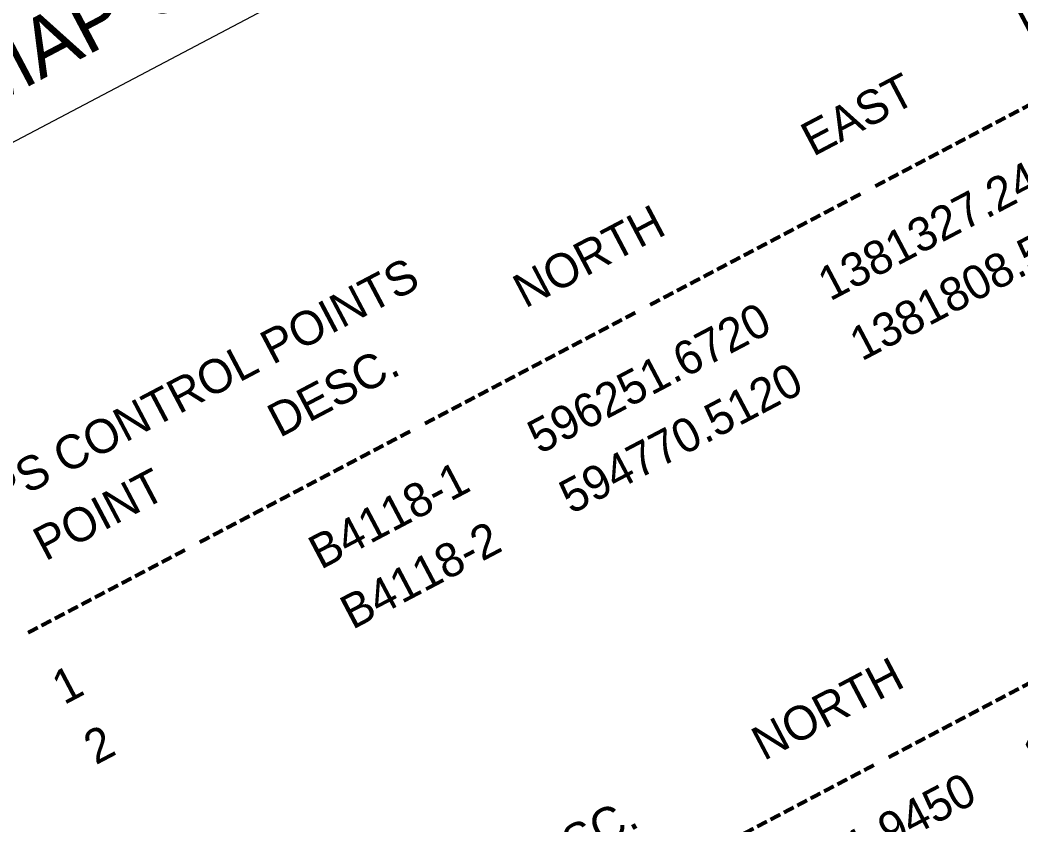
# Model space of a CAD drawing. Extents: x 1379448 to 1382868, y 593769 to 596827.
# Drawn here: x 1379935.9 to 1380243, y 594832.7 to 595079.7 of the extents above; entities that cross this region are included whole.
import ezdxf

# ---------------------------------------------------------------- set-up
doc = ezdxf.new("R2010")
doc.units = 0
for name, color, linetype in [('CTL Sheet Text', 7, 'Continuous'), ('Old_Level_1', 7, 'Continuous'), ('Old_Level_32', 7, 'Continuous')]:
    doc.layers.add(name, color=color, linetype=linetype)

msp = doc.modelspace()

# ---------------------------------------------------------------- linework, layer by layer
at = {"layer": 'Old_Level_1'}
msp.add_lwpolyline([(1379782.59, 595014.48), (1380447.79, 595365.17), (1380469.23, 595324.5), (1379804.02, 594973.82)], close=True, dxfattribs=at)

# ---------------------------------------------------------------- texts
at = {"layer": 'CTL Sheet Text'}
for s, height, p in [('    POINT          DESC.           NORTH             EAST          ELEVATION           L STATION       OFFSET', 10.41667, (1379930, 594906.31)), ('1                     B4118-1      596251.6720     1381327.2440           677.16         12+69.03        802.13 LT', 10.41667, (1379949.43, 594869.45)), ('2                     B4118-2      594770.5120     1381808.5600           655.74         10+96.75        740.30 RT', 10.41667, (1379959.15, 594851.03)), ('------------ ---------------- ---------------- ---------------- ---------------- ---------------- ----------------', 10.41667, (1379939.72, 594887.88)), ('    POINT          DESC.           NORTH             EAST          ELEVATION           L STATION       OFFSET', 10.41667, (1380003.19, 594767.49)), ('3                        BL-3      595511.9450     1381263.0910           673.40      OUTSIDE PROJECT LIMITS                 ', 10.41667, (1380022.62, 594730.63)), ('4                        BL-4      595437.7990     1381525.5930           667.25         10+68.66         17.88 RT', 10.41667, (1380032.34, 594712.2)), ('GPS CONTROL POINTS', 10.4167, (1379920.29, 594924.74)), ('------------ ---------------- ---------------- ---------------- ---------------- ---------------- ----------------', 10.41667, (1380012.9, 594749.06)), ('5                        BL-5      595615.1650     1381849.6980           663.12         14+30.97         13.34 RT', 10.41667, (1380042.05, 594693.77)), ('6                        BL-6      595829.4730     1381880.5770           670.58      OUTSIDE PROJECT LIMITS                 ', 10.41667, (1380051.77, 594675.34))]:
    msp.add_text(s, height=height, rotation=27.7977, dxfattribs=at).set_placement(p)
at = {"layer": 'Old_Level_32'}
msp.add_text('VICINITY MAP SHOWING LOCATION OF PROJECT B-4118', height=18, rotation=27.7977, dxfattribs=at).set_placement((1379828.68, 595001.39))

doc.saveas('drawing.dxf')
